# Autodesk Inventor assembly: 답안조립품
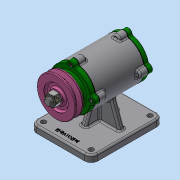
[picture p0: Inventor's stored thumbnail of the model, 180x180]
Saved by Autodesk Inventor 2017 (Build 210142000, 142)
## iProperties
Part Number: 답안조립품
Material: 일반
Document SubType Name: Assembly
Designer: MRC
Author: MRC
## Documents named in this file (12)
- C:\Users\MRC\Desktop\720716V1007\답안조립품.iam
- C:\Users\MRC\Desktop\720716V1007\본체.ipt
- C:\Users\MRC\Desktop\720716V1007\개스킷.ipt
- C:\Users\MRC\Desktop\720716V1007\앞커버.ipt
- C:\Users\MRC\Desktop\720716V1007\뒤커버.ipt
- C:\Users\MRC\Desktop\720716V1007\베어링 6204.ipt
- C:\Users\MRC\Desktop\720716V1007\오일 실.ipt
- C:\Users\MRC\Desktop\720716V1007\축.ipt
- C:\Users\MRC\Desktop\720716V1007\볼트 M4 x 12.ipt
- C:\Users\MRC\Desktop\720716V1007\키 4 x 4.ipt
- C:\Users\MRC\Desktop\720716V1007\V-벨트풀리.ipt
- C:\Users\MRC\Desktop\720716V1007\너트 M12 x 1.25.ipt
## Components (3 placed, 2 different names)
1. 개스킷:1
2. 개스킷:2
3. V-벨트풀리:1
